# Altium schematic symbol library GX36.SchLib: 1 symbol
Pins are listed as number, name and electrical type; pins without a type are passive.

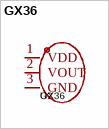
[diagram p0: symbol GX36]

## GX36
designator U?
footprint TO-92-3_L4.9-W3.7-P1.27-L
pins: 1 VDD, 2 VOUT, 3 GND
